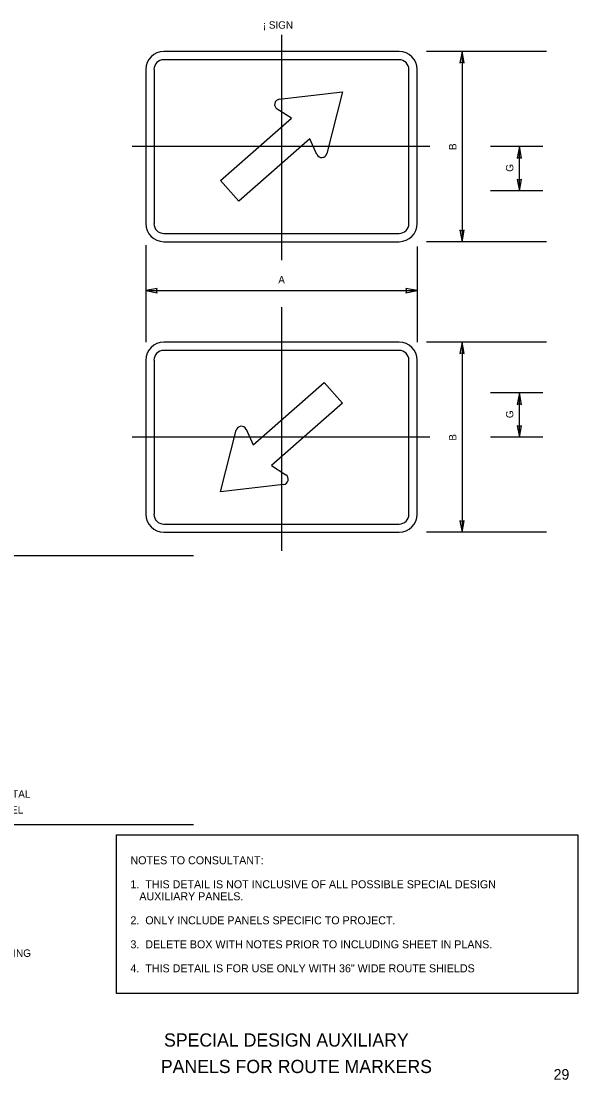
# Model space of a CAD drawing. Extents: x 60714 to 61343, y 8039 to 8449.
# Drawn here: x 61132.8 to 61343.3, y 8049.1 to 8449.1 of the extents above; entities that cross this region are included whole.
import ezdxf

# ---------------------------------------------------------------- set-up
doc = ezdxf.new("R2010")
doc.units = 0
for name, color, linetype in [('DimLines_dp', 7, 'Continuous'), ('SignPanel', 7, 'Continuous'), ('TextAlert', 7, 'Continuous'), ('TextMisc', 7, 'Continuous'), ('TextNotes', 7, 'Continuous'), ('TextShtNo', 7, 'Continuous')]:
    doc.layers.add(name, color=color, linetype=linetype)

msp = doc.modelspace()

# ---------------------------------------------------------------- linework, layer by layer
at = {"layer": 'DimLines_dp'}
for p, q in [((61231.24, 8444.01), (61231.24, 8358.79)), ((61331.48, 8437.66), (61286.1, 8437.66)), ((61299.55, 8437.66), (61298.71, 8433.31)), ((61299.55, 8437.66), (61299.55, 8365.8)), ((61300.36, 8433.31), (61299.55, 8437.66)), ((61298.71, 8433.31), (61299.55, 8433.64)), ((61299.55, 8433.64), (61300.36, 8433.31)), ((61287.35, 8401.73), (61174.81, 8401.73)), ((61330.11, 8401.73), (61310.29, 8401.73)), ((61321.21, 8401.73), (61320.37, 8397.38)), ((61321.21, 8384.99), (61321.21, 8401.73)), ((61322.02, 8397.38), (61321.21, 8401.73)), ((61320.37, 8397.38), (61321.21, 8397.71)), ((61321.21, 8397.71), (61322.02, 8397.38)), ((61321.21, 8389.01), (61320.4, 8389.34)), ((61320.4, 8389.34), (61321.21, 8384.99)), ((61321.21, 8384.99), (61322.05, 8389.34)), ((61322.05, 8389.34), (61321.21, 8389.01)), ((61330.11, 8384.99), (61310.29, 8384.99)), ((61299.55, 8369.82), (61298.74, 8370.15)), ((61298.74, 8370.15), (61299.55, 8365.8)), ((61299.55, 8365.8), (61300.39, 8370.15)), ((61300.39, 8370.15), (61299.55, 8369.82)), ((61179.91, 8364.46), (61179.91, 8327.85)), ((61282.58, 8364.01), (61282.58, 8327.85)), ((61331.48, 8365.8), (61286.1, 8365.8)), ((61184.26, 8348.12), (61179.91, 8347.31)), ((61183.93, 8347.31), (61184.26, 8348.12)), ((61282.58, 8347.31), (61278.23, 8348.15)), ((61278.23, 8348.15), (61278.56, 8347.31)), ((61179.91, 8347.31), (61282.58, 8347.31)), ((61179.91, 8347.31), (61184.26, 8346.47)), ((61184.26, 8346.47), (61183.93, 8347.31)), ((61278.56, 8347.31), (61278.23, 8346.5)), ((61278.23, 8346.5), (61282.58, 8347.31)), ((61231.24, 8341.08), (61231.24, 8248.98)), ((61331.48, 8327.85), (61286.1, 8327.85)), ((61299.55, 8327.85), (61298.71, 8323.5)), ((61299.55, 8327.85), (61299.55, 8255.99)), ((61300.36, 8323.5), (61299.55, 8327.85)), ((61298.71, 8323.5), (61299.55, 8323.83)), ((61299.55, 8323.83), (61300.36, 8323.5)), ((61330.11, 8308.67), (61310.29, 8308.67)), ((61321.21, 8308.66), (61320.37, 8304.31)), ((61321.21, 8291.92), (61321.21, 8308.67)), ((61322.02, 8304.31), (61321.21, 8308.66)), ((61320.37, 8304.31), (61321.21, 8304.64)), ((61321.21, 8304.64), (61322.02, 8304.31)), ((61321.21, 8295.94), (61320.4, 8296.27)), ((61320.4, 8296.27), (61321.21, 8291.92)), ((61321.21, 8291.92), (61322.05, 8296.27)), ((61322.05, 8296.27), (61321.21, 8295.94)), ((61287.35, 8291.92), (61174.81, 8291.92)), ((61330.11, 8291.92), (61310.29, 8291.92)), ((61299.55, 8260.01), (61298.74, 8260.34)), ((61298.74, 8260.34), (61299.55, 8255.99)), ((61299.55, 8255.99), (61300.39, 8260.34)), ((61300.39, 8260.34), (61299.55, 8260.01)), ((61331.48, 8255.99), (61286.1, 8255.99))]:
    msp.add_line(p, q, dxfattribs=at)
at = {"layer": 'SignPanel'}
for p, q in [((61230.41, 8419.58), (61254.31, 8422.42)), ((61254.31, 8422.42), (61248.38, 8399.1)), ((61235.04, 8412.49), (61229.59, 8415.91)), ((61208.18, 8388.93), (61235.04, 8412.49)), ((61241.95, 8404.61), (61215.09, 8381.05)), ((61244.63, 8398.76), (61241.95, 8404.61)), ((61215.09, 8381.05), (61208.18, 8388.93)), ((61220.53, 8289.04), (61247.39, 8312.61)), ((61247.39, 8312.61), (61254.31, 8304.73)), ((61254.31, 8304.73), (61227.44, 8281.17)), ((61208.18, 8271.24), (61214.1, 8294.56)), ((61217.85, 8294.9), (61220.53, 8289.04)), ((61227.44, 8281.17), (61232.9, 8277.75)), ((61232.07, 8274.07), (61208.18, 8271.24))]:
    msp.add_line(p, q, dxfattribs=at)
for points in [[(61275.73, 8437.66), (61186.75, 8437.66)], [(61275.73, 8434.53), (61186.75, 8434.53)], [(61179.91, 8430.82), (61179.91, 8372.64)], [(61183.05, 8430.82), (61183.05, 8372.64)], [(61279.44, 8372.64), (61279.44, 8430.82)], [(61282.58, 8372.64), (61282.58, 8430.82)], [(61186.75, 8368.93), (61275.73, 8368.93)], [(61186.75, 8365.8), (61275.73, 8365.8)], [(61275.73, 8327.85), (61186.75, 8327.85)], [(61275.73, 8324.72), (61186.75, 8324.72)], [(61179.91, 8321.01), (61179.91, 8262.83)], [(61183.05, 8321.01), (61183.05, 8262.83)], [(61279.44, 8262.83), (61279.44, 8321.01)], [(61282.58, 8262.83), (61282.58, 8321.01)], [(61186.75, 8259.12), (61275.73, 8259.12)], [(61186.75, 8255.99), (61275.73, 8255.99)]]:
    msp.add_lwpolyline(points, dxfattribs=at)
for centre, radius, start, end in [((61186.75, 8430.82), 6.84, 90, 180), ((61275.73, 8430.82), 6.84, 360, 90), ((61186.75, 8430.82), 3.71, 90, 179.9456), ((61275.73, 8430.82), 3.71, 0.0544, 90), ((61230.65, 8417.6), 2, 96.7689, 237.9013), ((61246.45, 8399.59), 2, 204.6127, 345.7451), ((61186.75, 8372.64), 6.84, 180, 270), ((61186.75, 8372.64), 3.71, 180, 270), ((61275.73, 8372.64), 6.84, 270, 0), ((61275.73, 8372.64), 3.71, 270, 0), ((61186.75, 8321.01), 6.84, 90, 180), ((61275.73, 8321.01), 6.84, 360, 90), ((61186.75, 8321.01), 3.71, 90, 179.9456), ((61275.73, 8321.01), 3.71, 0.0544, 90), ((61216.04, 8294.06), 2, 24.6127, 165.7451), ((61231.84, 8276.05), 2, 276.7689, 57.9013), ((61186.75, 8262.83), 6.84, 180, 270), ((61186.75, 8262.83), 3.71, 180, 270), ((61275.73, 8262.83), 6.84, 270, 0), ((61275.73, 8262.83), 3.71, 270, 0)]:
    msp.add_arc(centre, radius, start, end, dxfattribs=at)
at = {"layer": 'TextAlert'}
msp.add_lwpolyline([(61168.9, 8141.64), (61343.32, 8141.64), (61343.32, 8081.68), (61168.9, 8081.68)], close=True, dxfattribs=at)
at = {"layer": 'TextNotes'}
for p, q in [((61037.66, 8247.22), (61197.94, 8247.22)), ((61197.94, 8145.52), (61037.66, 8145.52))]:
    msp.add_line(p, q, dxfattribs=at)

# ---------------------------------------------------------------- texts
at = {"layer": 'DimLines_dp'}
for s, p in [('¡ SIGN', (61224.18, 8446.27)), ('A', (61230.04, 8350.03))]:
    msp.add_text(s, height=2.8, dxfattribs=at).set_placement(p)
for s, p in [('B', (61297.41, 8400.43)), ('G', (61318.94, 8392.2)), ('G', (61318.94, 8299.13)), ('B', (61297.41, 8290.62))]:
    msp.add_text(s, height=2.8, rotation=90, dxfattribs=at).set_placement(p)
at = {"layer": 'TextAlert'}
for s, p in [('NOTES TO CONSULTANT:', (61174.14, 8130.56)), ('1.  THIS DETAIL IS NOT INCLUSIVE OF ALL POSSIBLE SPECIAL DESIGN', (61174.14, 8121.49)), ('   AUXILIARY PANELS.', (61174.14, 8116.95)), ('2.  ONLY INCLUDE PANELS SPECIFIC TO PROJECT.', (61174.14, 8107.88)), ('3.  DELETE BOX WITH NOTES PRIOR TO INCLUDING SHEET IN PLANS.', (61174.14, 8098.81)), ('4.  THIS DETAIL IS FOR USE ONLY WITH 36" WIDE ROUTE SHIELDS', (61174.14, 8089.74))]:
    msp.add_text(s, height=3.024, dxfattribs=at).set_placement(p)
at = {"layer": 'TextMisc'}
for s, p in [('SPECIAL DESIGN AUXILIARY', (61186.84, 8061.67)), ('PANELS FOR ROUTE MARKERS', (61185.63, 8051.67))]:
    msp.add_text(s, height=5, rotation=360, dxfattribs=at).set_placement(p)
at = {"layer": 'TextNotes'}
for s, p in [('FABRICATOR SHALL OPTICALLY CENTER (HORIZONTAL', (61034.77, 8155.72)), ('AND VERTICAL) THE ARROW WITHIN THE SIGN PANEL', (61034.77, 8149.7)), ('DIAMOND GRADE CUBED (DG3) REFLECTIVE SHEETING', (61034.77, 8095.58))]:
    msp.add_text(s, height=2.8, dxfattribs=at).set_placement(p)
at = {"layer": 'TextShtNo'}
msp.add_text('29', height=4, rotation=360, dxfattribs=at).set_placement((61334.15, 8049.17))

doc.saveas('drawing.dxf')
